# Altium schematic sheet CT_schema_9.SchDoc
size 274 x 160 mm
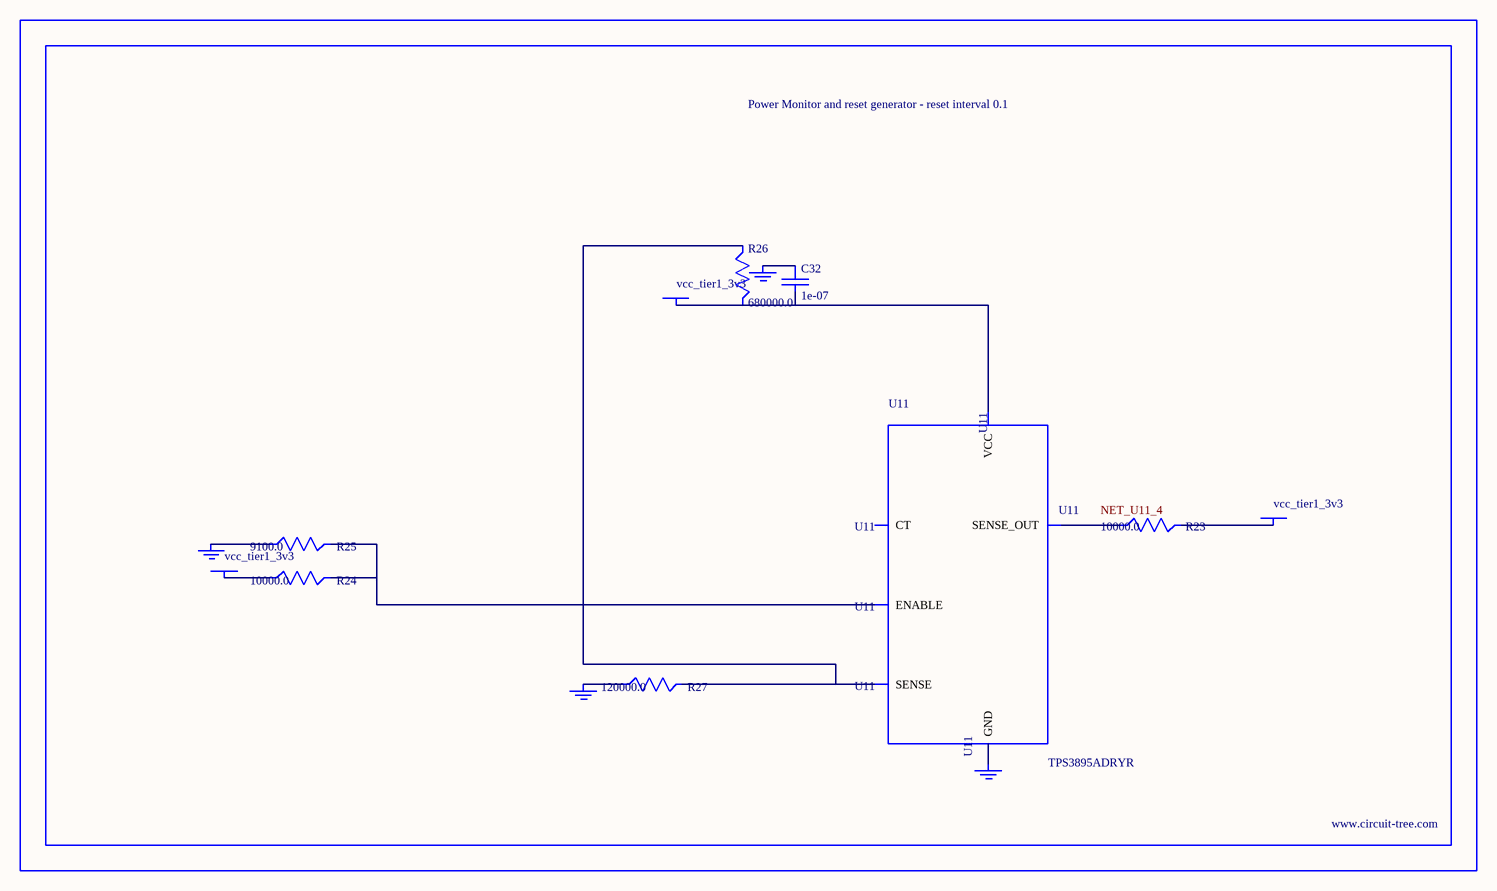
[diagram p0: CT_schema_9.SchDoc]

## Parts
BORDER8  (no value)
C32  1e-07  [C0402]
GND_INSTANCE_8_0  (no value)
GND_INSTANCE_8_1  (no value)
GND_INSTANCE_8_2  (no value)
GND_INSTANCE_8_3  (no value)
POWER_INSTANCE_8_0  vcc_tier1_3v3
POWER_INSTANCE_8_1  vcc_tier1_3v3
POWER_INSTANCE_8_2  vcc_tier1_3v3
R23  10000.0  [R0603]
R24  10000.0  [R0603]
R25  9100.0  [R0603]
R26  680000.0  [R0603]
R27  120000.0  [R0603]
U11  TPS3895ADRYR  [SON-6]

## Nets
NetC32_1: C32.1 GND_INSTANCE_8_2.0(GND)
NetC32_2: C32.2 POWER_INSTANCE_8_2.0(PWR) R26.2 U11.6(VCC)
NetGND_INSTANCE_8_0_0: GND_INSTANCE_8_0.0(GND) R25.1
NetGND_INSTANCE_8_1_0: GND_INSTANCE_8_1.0(GND) R27.1
NetGND_INSTANCE_8_3_0: GND_INSTANCE_8_3.0(GND) U11.2(GND)
NetPOWER_INSTANCE_8_0_0: POWER_INSTANCE_8_0.0(PWR) R24.1
NetPOWER_INSTANCE_8_1_0: POWER_INSTANCE_8_1.0(PWR) R23.2
NetR23_1: R23.1 U11.4(SENSE_OUT)
NetR24_2: R24.2 R25.2 U11.1(ENABLE)
NetR26_1: R26.1 R27.2 U11.3(SENSE)

Not connected (* = marked no-connect by the designer): U11 5(CT)

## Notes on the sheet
- Labels drawn without touching a wire or pin: NET_U11_4

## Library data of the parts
BORDER8 = BORDER_PAGE8
C32 = C0402C104K3RACTU
GND_INSTANCE_8_0-GND_INSTANCE_8_3 = GND
POWER_INSTANCE_8_0-POWER_INSTANCE_8_2 = PWR
R23 R24 = RC0603JR-0710KL
R25 = RC0603JR-079K1L
R26 = RC0603JR-07680KL
R27 = RC0603JR-07120KL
